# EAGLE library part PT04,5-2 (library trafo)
TRANSFORMER 1 primary winding, temp. protection fuse, 2 secondary windings/ mounting hole BLOCK
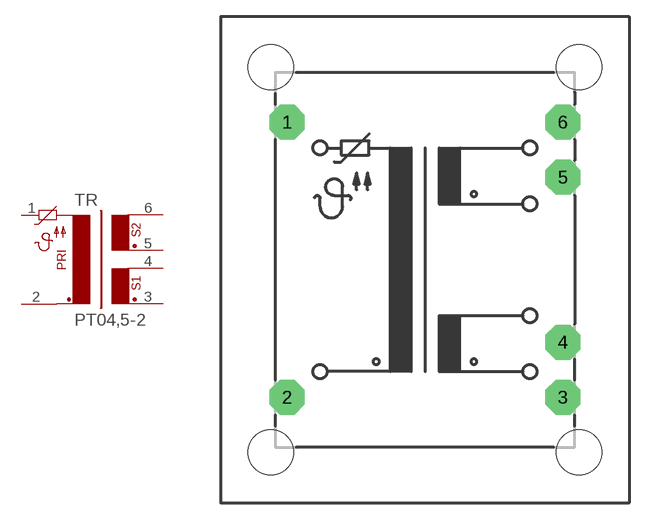
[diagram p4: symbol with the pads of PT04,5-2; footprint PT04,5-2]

Designator prefix TR

## PT04,5-2  [PT04,5-2]
1  1  pas
2  2  pas
3  3  pas
4  4  pas
5  5  pas
6  6  pas

## Footprint PT04,5-2 (pad centres in mm)
TRANSFORMER 1 primary winding, 2 secondary windings, temp. protection fuse, mounting holes
drill 1.397 pad 3.175 octagon: 1 -12.522,12.497; 2 -12.522,-12.497; 3 12.522,-12.497; 4 12.522,-7.493; 5 12.522,7.493; 6 12.522,12.497
hole 4.115 at -13.995,-17.501
hole 4.115 at -13.995,17.501
hole 4.115 at 13.995,17.501
hole 4.115 at 13.995,-17.501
